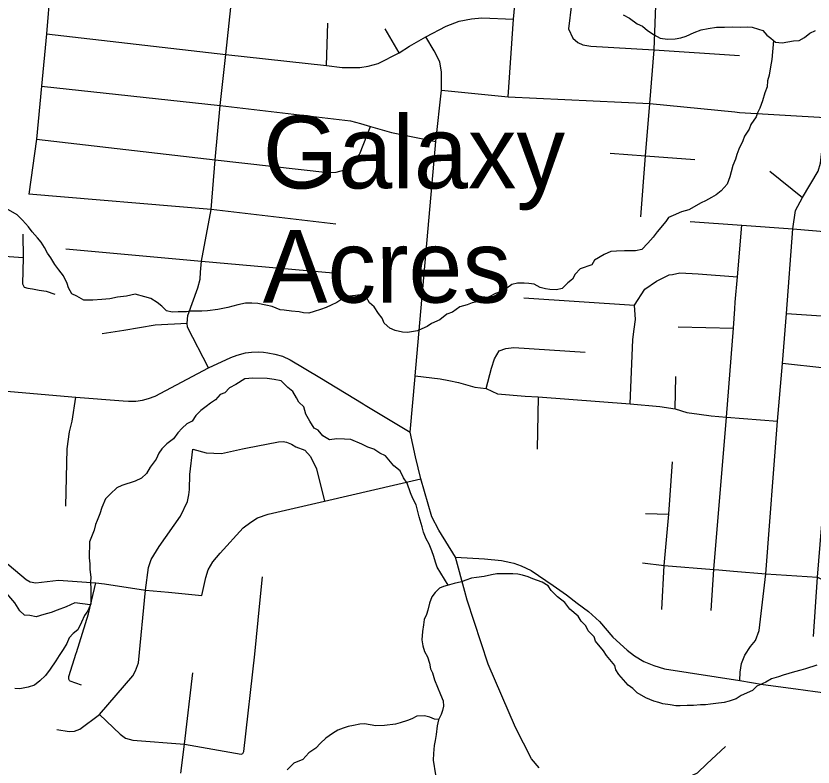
# Model space of a CAD drawing. Extents: x 0 to 69.5, y -4.5 to 22.
# Drawn here: x 4.554 to 5.421, y 16.285 to 17.102 of the extents above; entities that cross this region are included whole.
import ezdxf

# ---------------------------------------------------------------- set-up
doc = ezdxf.new("R2010")
doc.units = 0
for name, color, linetype in [('GM_X_County_Road', 7, 'Continuous'), ('GM_X_Minor_River', 7, 'Continuous'), ('GM_X_Township_Subdivision', 7, 'Continuous'), ('GM_X_Unincorporated_Text', 7, 'Continuous')]:
    doc.layers.add(name, color=color, linetype=linetype)

msp = doc.modelspace()

# ---------------------------------------------------------------- linework, layer by layer
at = {"layer": 'GM_X_County_Road'}
for points in [[(4.98809, 16.70952), (4.98815, 16.71012), (5.01058, 16.96502), (5.01675, 17.02076), (5.08927, 17.01363), (5.09515, 17.09796), (5.11236, 17.27796)], [(5.08927, 17.01363), (5.24337, 17.00629), (5.33573, 16.9972)], [(5.33573, 16.9972), (5.34088, 16.9967), (5.4342, 16.99118), (5.44574, 16.99168), (5.45778, 16.99319), (5.47383, 16.99921), (5.48558, 17.00366)], [(4.5229, 16.69542), (4.6194, 16.68687), (4.67069, 16.68292), (4.67645, 16.68276), (4.68435, 16.68276), (4.69158, 16.68358), (4.69815, 16.68539), (4.70555, 16.68819), (4.76358, 16.71876), (4.78792, 16.7301), (4.79466, 16.73257), (4.8037, 16.73504), (4.81044, 16.73586), (4.81734, 16.73636), (4.82327, 16.73603), (4.8282, 16.73521), (4.83576, 16.73389), (4.84414, 16.73142), (4.8522, 16.72748), (4.88475, 16.70857), (4.93159, 16.6799)], [(4.98273, 16.64889), (4.98809, 16.70952)], [(4.93159, 16.6799), (4.93391, 16.67848), (4.98273, 16.64889)], [(5.03222, 16.51309), (5.01381, 16.5422), (5.00625, 16.55682), (4.99457, 16.59809), (4.98866, 16.62209), (4.98273, 16.64889)], [(5.04216, 16.47567), (5.03222, 16.51309)], [(5.03222, 16.51309), (5.06379, 16.51128), (5.08203, 16.50931), (5.09237, 16.50719)], [(5.09237, 16.50719), (5.09568, 16.50652), (5.10341, 16.50372), (5.11443, 16.49863), (5.13842, 16.48218), (5.15273, 16.47216), (5.16457, 16.46311), (5.17673, 16.45407), (5.18882, 16.4429), (5.2032, 16.42612), (5.21866, 16.41182), (5.22671, 16.40574), (5.2369, 16.39949), (5.24792, 16.39505), (5.25926, 16.3916), (5.3413, 16.37894), (5.36662, 16.37466), (5.40213, 16.36974), (5.42309, 16.36686), (5.44274, 16.36431), (5.44492, 16.36412)], [(5.12307, 16.28389), (5.11471, 16.29382), (5.09721, 16.32776), (5.06762, 16.39671), (5.04464, 16.46635), (5.04216, 16.47567)]]:
    msp.add_lwpolyline(points, dxfattribs=at)
at = {"layer": 'GM_X_Minor_River'}
for points in [[(5.21444, 17.10287), (5.22119, 17.09925), (5.22976, 17.09292), (5.2354, 17.09048), (5.24097, 17.08575), (5.24807, 17.08098), (5.25482, 17.07737), (5.26278, 17.07639), (5.27115, 17.07654), (5.27727, 17.07789), (5.28302, 17.07963), (5.29149, 17.08359), (5.29917, 17.08642), (5.30683, 17.08811), (5.31599, 17.08937), (5.32474, 17.08951), (5.33387, 17.08964), (5.34223, 17.08941), (5.34946, 17.08959), (5.35478, 17.08944), (5.36157, 17.08734), (5.36646, 17.08569), (5.37051, 17.08062), (5.37499, 17.07745), (5.3802, 17.07312), (5.3874, 17.07254), (5.39963, 17.07448), (5.40573, 17.07507), (5.41152, 17.07834), (5.41734, 17.08275), (5.42351, 17.08562)], [(5.37806, 17.0749), (5.37626, 17.05419), (5.37452, 17.04624), (5.37313, 17.03714), (5.37145, 17.03109), (5.37089, 17.02463), (5.36843, 17.01785), (5.36591, 17.00916), (5.36303, 17.00124), (5.36062, 16.99636), (5.35898, 16.99184), (5.35343, 16.98361), (5.35138, 16.97834), (5.34624, 16.97087), (5.34458, 16.96596), (5.34015, 16.95656), (5.33809, 16.95091), (5.33644, 16.94601), (5.33358, 16.93885), (5.33187, 16.93204), (5.33059, 16.92675), (5.32771, 16.91883), (5.32105, 16.9114), (5.3156, 16.90698), (5.31058, 16.90407), (5.30402, 16.90045), (5.29939, 16.89829), (5.28588, 16.89067), (5.27784, 16.88861), (5.26898, 16.88467), (5.2636, 16.88254), (5.26082, 16.87804), (5.25139, 16.86688), (5.24704, 16.86091), (5.24117, 16.8546), (5.23489, 16.84754), (5.22801, 16.84621), (5.21584, 16.84617), (5.20708, 16.84565), (5.20099, 16.84544), (5.19367, 16.84221), (5.18324, 16.83603), (5.18043, 16.83078), (5.16777, 16.82656), (5.16229, 16.82062), (5.15948, 16.81537), (5.15443, 16.81132), (5.14817, 16.80502), (5.14205, 16.80367), (5.13484, 16.80425), (5.12991, 16.80477), (5.12425, 16.80645), (5.11751, 16.81006), (5.11182, 16.8106), (5.10689, 16.81112), (5.09966, 16.81094), (5.09353, 16.80959), (5.08384, 16.80262), (5.07578, 16.7998), (5.06883, 16.79619), (5.06269, 16.79407), (5.05576, 16.79084), (5.0504, 16.78947), (5.04463, 16.78734), (5.03697, 16.78527), (5.02883, 16.77941), (5.02269, 16.77729), (5.01491, 16.77103), (5.00606, 16.76709), (5.0014, 16.7638), (4.99563, 16.76129), (4.99063, 16.75915), (4.97993, 16.75716), (4.97462, 16.75769), (4.96668, 16.75943), (4.96066, 16.76188), (4.95472, 16.76738), (4.95221, 16.77278), (4.94854, 16.77784), (4.9438, 16.7852), (4.9386, 16.78954), (4.93533, 16.79534), (4.92856, 16.79819), (4.92322, 16.79758), (4.91674, 16.797), (4.90944, 16.79416), (4.90324, 16.79014), (4.89707, 16.78689), (4.8913, 16.78438), (4.88516, 16.78227), (4.87826, 16.78018), (4.8725, 16.77843), (4.8668, 16.77859), (4.86228, 16.77986), (4.85392, 16.78048), (4.84596, 16.78146), (4.84142, 16.78197), (4.83277, 16.78563), (4.82596, 16.78697), (4.81726, 16.78873), (4.81081, 16.7893)], [(4.81081, 16.7893), (4.80358, 16.78912), (4.79555, 16.78744), (4.78445, 16.7847), (4.77374, 16.78233), (4.76228, 16.78075), (4.75619, 16.78054), (4.75163, 16.78066), (4.74402, 16.7805), (4.73944, 16.77986), (4.73069, 16.77973), (4.72384, 16.77954), (4.71779, 16.78085), (4.71261, 16.78594), (4.70777, 16.78988), (4.70066, 16.79427), (4.69424, 16.79597), (4.68368, 16.79894), (4.67449, 16.79691), (4.66457, 16.79566), (4.65616, 16.79399), (4.64739, 16.79309), (4.63787, 16.7926), (4.63292, 16.79236), (4.62798, 16.79249), (4.62049, 16.79689), (4.61485, 16.79933), (4.61123, 16.80591), (4.60984, 16.81052), (4.60588, 16.81901), (4.60074, 16.82562), (4.59633, 16.83146), (4.59196, 16.83844), (4.58829, 16.84349), (4.58504, 16.84967), (4.58139, 16.85548), (4.57772, 16.86016), (4.57181, 16.8668), (4.56778, 16.87224), (4.56113, 16.87966), (4.55558, 16.88515), (4.5436, 16.89234)], [(5.0243, 16.48247), (5.01218, 16.50226), (5.01042, 16.50764), (5.00869, 16.51378), (5.0062, 16.51995), (5.00335, 16.52726), (5.00009, 16.53306), (4.99723, 16.54), (4.99588, 16.54613), (4.99274, 16.55688), (4.9893, 16.56992), (4.98568, 16.57688), (4.98319, 16.58304), (4.97967, 16.59342), (4.97564, 16.59924), (4.97205, 16.60696), (4.96497, 16.61249), (4.95613, 16.62302), (4.94975, 16.62624), (4.94341, 16.63061), (4.93662, 16.6327), (4.93024, 16.63593), (4.91821, 16.64083), (4.91138, 16.6414), (4.90302, 16.64164), (4.89501, 16.64072), (4.8879, 16.6451), (4.88274, 16.65096), (4.87824, 16.65337), (4.87387, 16.66073), (4.86952, 16.66846), (4.86708, 16.67653), (4.86189, 16.68162), (4.85935, 16.68626), (4.85536, 16.69323), (4.84977, 16.69758), (4.84236, 16.70464), (4.8348, 16.70637), (4.82722, 16.70734), (4.81164, 16.70778), (4.80287, 16.70688), (4.7932, 16.70068), (4.78625, 16.69706), (4.78117, 16.69187), (4.77617, 16.68973), (4.77107, 16.68416), (4.76565, 16.6805), (4.76098, 16.67682), (4.75516, 16.67242), (4.7497, 16.66724), (4.74572, 16.66087), (4.73994, 16.65799), (4.73486, 16.65318), (4.73017, 16.64836), (4.72542, 16.64164), (4.71805, 16.63613), (4.71258, 16.63095), (4.70941, 16.62609), (4.70657, 16.6197), (4.70025, 16.61073), (4.69626, 16.60399), (4.69079, 16.59881), (4.68386, 16.59558), (4.66929, 16.59104), (4.6639, 16.58852), (4.65687, 16.58186), (4.65139, 16.5763), (4.64734, 16.5669), (4.64525, 16.5601), (4.64239, 16.55294), (4.64075, 16.54842), (4.63906, 16.54237), (4.63621, 16.53522), (4.63415, 16.52956), (4.63369, 16.51244), (4.63464, 16.50556), (4.63448, 16.49947), (4.63539, 16.49107), (4.63525, 16.48574), (4.63542, 16.47812), (4.63563, 16.47164), (4.63537, 16.46213), (4.63212, 16.4546), (4.62856, 16.44937), (4.62532, 16.44223), (4.62129, 16.43396), (4.61624, 16.42991), (4.61192, 16.42508), (4.60948, 16.41906), (4.6055, 16.41269), (4.60114, 16.40596), (4.59756, 16.40035), (4.59122, 16.39101), (4.5861, 16.38429), (4.58023, 16.37837), (4.57441, 16.37396), (4.5675, 16.37148), (4.55833, 16.36984), (4.55301, 16.36999)], [(4.63495, 16.46116), (4.61829, 16.46337), (4.60866, 16.45907), (4.59906, 16.45552), (4.59252, 16.45266), (4.58448, 16.4506), (4.57604, 16.44817), (4.56923, 16.4495), (4.56354, 16.45004), (4.55835, 16.45476), (4.55288, 16.46329), (4.54624, 16.47109), (4.5422, 16.47615), (4.53667, 16.48278), (4.53263, 16.48784), (4.52933, 16.49251), (4.52263, 16.49802), (4.50969, 16.50217)], [(5.18454, 16.42168), (5.18277, 16.4263), (5.17648, 16.43295), (5.17397, 16.43835), (5.16878, 16.44344), (5.16551, 16.44887), (5.15658, 16.45635), (5.15108, 16.46374), (5.14288, 16.46968), (5.13622, 16.47672), (5.13294, 16.48176), (5.1262, 16.48576), (5.11603, 16.48947), (5.11114, 16.49151), (5.10511, 16.49358), (5.09981, 16.49449), (5.09451, 16.49502), (5.08728, 16.49484), (5.08234, 16.49498), (5.07701, 16.49474), (5.07128, 16.49376), (5.06324, 16.49208), (5.05484, 16.49079), (5.0495, 16.49018), (5.04336, 16.48807), (5.03875, 16.48629), (5.03071, 16.48423), (5.02572, 16.48284), (5.01921, 16.48112), (5.0146, 16.47935), (5.00991, 16.47453), (5.00635, 16.46968), (5.00389, 16.46289), (5.00216, 16.45532), (5.00051, 16.4508), (4.99808, 16.44515), (4.99717, 16.43947), (4.99621, 16.43226), (4.99558, 16.42314), (4.99655, 16.41664), (4.99828, 16.4105), (5.00155, 16.40469), (5.00402, 16.39777), (5.00499, 16.39165), (5.00715, 16.38702), (5.00924, 16.37973), (5.01564, 16.36355), (5.01888, 16.35661), (5.0191, 16.35089), (5.01784, 16.34636), (5.01657, 16.34182), (5.01376, 16.33619), (5.01205, 16.32938), (5.01105, 16.32027), (5.0101, 16.31344), (5.00881, 16.30815), (5.0082, 16.29941), (5.008, 16.29218), (5.01023, 16.27612)], [(5.42494, 16.39556), (5.41267, 16.39172), (5.40767, 16.38995), (5.40078, 16.38824), (5.38852, 16.38477), (5.38353, 16.38301), (5.37585, 16.38056), (5.36967, 16.37692), (5.35967, 16.37263), (5.35497, 16.36781), (5.34266, 16.36244), (5.33723, 16.35878), (5.32956, 16.35633), (5.3242, 16.35496), (5.31504, 16.35369), (5.30932, 16.35309), (5.30398, 16.35248), (5.29865, 16.35224), (5.29103, 16.35169), (5.28418, 16.3515), (5.27657, 16.35133), (5.27163, 16.35147), (5.26557, 16.3524), (5.25761, 16.35338), (5.25309, 16.35503), (5.2478, 16.35632), (5.23915, 16.35999), (5.2298, 16.36558), (5.22498, 16.37029), (5.21975, 16.37386), (5.20981, 16.38556), (5.20652, 16.3906), (5.2055, 16.3952), (5.19629, 16.40612), (5.19301, 16.41116), (5.18454, 16.42168)], [(5.01396, 16.33659), (5.00921, 16.3367), (5.00433, 16.33912), (4.99828, 16.34043), (4.9899, 16.3399), (4.9845, 16.337), (4.97989, 16.33523), (4.97183, 16.33279), (4.96685, 16.3314), (4.95502, 16.32983), (4.94551, 16.32971), (4.93945, 16.33064), (4.93301, 16.33159), (4.92806, 16.33134), (4.92118, 16.33001), (4.91544, 16.32865), (4.91007, 16.32689), (4.90431, 16.32477), (4.8985, 16.32112), (4.89114, 16.316), (4.88529, 16.31083), (4.8802, 16.30526), (4.87246, 16.30014), (4.86618, 16.29308), (4.85617, 16.28879), (4.84914, 16.28175)]]:
    msp.add_lwpolyline(points, dxfattribs=at)
at = {"layer": 'GM_X_Township_Subdivision'}
for points in [[(5.2336, 16.88318), (5.23886, 16.94949), (5.24337, 17.00629), (5.24801, 17.06473), (5.24996, 17.11306), (5.25136, 17.12144), (5.25535, 17.13142), (5.2753, 17.16534), (5.30483, 17.21722)], [(4.59116, 17.13115), (4.58739, 17.08214), (4.58173, 17.02521), (4.57646, 16.96752), (4.5683, 16.90769)], [(5.1581, 17.11458), (5.15485, 17.0876), (5.15982, 17.07727), (5.16514, 17.0729), (5.17054, 17.07016), (5.17932, 17.06876), (5.24801, 17.06473), (5.34095, 17.05858)], [(4.76358, 16.71876), (4.74063, 16.76321), (4.74033, 16.76765), (4.74107, 16.77578), (4.75204, 16.80587), (4.75456, 16.81531), (4.75475, 16.82291), (4.75594, 16.83508), (4.76629, 16.89117), (4.77063, 16.94509), (4.77628, 17.00418), (4.7825, 17.05961), (4.78797, 17.1107)], [(4.58739, 17.08214), (4.7825, 17.05961), (4.89175, 17.04782), (4.90872, 17.04538), (4.92813, 17.04538), (4.93699, 17.04698), (4.94793, 17.0499), (4.97074, 17.06159), (4.98206, 17.06886), (4.9997, 17.07897), (5.02211, 17.09062), (5.03599, 17.09596), (5.04961, 17.09862), (5.06076, 17.0995), (5.09515, 17.09796)], [(4.89175, 17.04782), (4.89322, 17.09371)], [(4.97074, 17.06159), (4.95575, 17.0876)], [(5.01675, 17.02076), (5.01705, 17.04057), (5.01492, 17.05172), (5.00891, 17.06376), (4.9997, 17.07897)], [(4.58173, 17.02521), (4.77628, 17.00418), (4.91786, 16.98741), (4.92879, 16.98477), (4.93954, 16.98137), (4.95236, 16.9776), (4.96254, 16.97478), (5.01058, 16.96502)], [(5.3413, 16.37894), (5.34163, 16.38798), (5.34295, 16.39752), (5.34689, 16.4064), (5.35281, 16.41577), (5.35825, 16.4223), (5.36231, 16.43329), (5.36946, 16.49489), (5.38216, 16.66076), (5.38756, 16.7235), (5.39207, 16.7781), (5.39883, 16.87016), (5.40181, 16.89013), (5.4096, 16.90411), (5.42641, 16.93278), (5.42906, 16.94163), (5.43137, 16.96075), (5.4342, 16.99118)], [(4.57646, 16.96752), (4.77063, 16.94509), (4.89316, 16.93142), (4.9024, 16.9316), (4.91164, 16.93424), (4.92013, 16.94148), (4.92766, 16.95102), (4.93238, 16.9629), (4.93954, 16.98137)], [(5.20039, 16.95252), (5.23886, 16.94949), (5.29223, 16.94545)], [(5.37384, 16.93296), (5.4096, 16.90411)], [(4.90215, 16.87508), (4.76629, 16.89117), (4.5683, 16.90769)], [(5.28716, 16.87821), (5.34366, 16.87393), (5.39883, 16.87016), (5.45446, 16.86522), (5.48021, 16.86333)], [(5.33638, 16.79021), (5.33862, 16.81775), (5.34366, 16.87393)], [(4.56151, 16.86418), (4.56211, 16.83865), (4.56136, 16.81039), (4.56299, 16.80655), (4.56714, 16.80537), (4.57216, 16.80492), (4.57941, 16.8033), (4.58695, 16.80241), (4.59657, 16.79886)], [(5.39207, 16.7781), (5.43543, 16.77527), (5.44446, 16.77438), (5.44836, 16.7773), (5.45446, 16.86522)], [(4.56211, 16.83865), (4.43076, 16.84811), (4.33929, 16.85497)], [(4.60854, 16.84819), (4.75594, 16.83508), (4.89892, 16.82236)], [(5.22643, 16.76078), (5.22776, 16.77165), (5.22677, 16.78695), (5.2381, 16.8043), (5.25084, 16.81314), (5.26465, 16.81987), (5.26792, 16.82058)], [(5.26792, 16.82058), (5.27597, 16.82235), (5.29615, 16.82128), (5.33862, 16.81775)], [(5.10642, 16.79509), (5.22677, 16.78695)], [(5.31011, 16.45509), (5.31318, 16.49968), (5.32677, 16.66518), (5.33438, 16.76217), (5.3358, 16.78306), (5.33638, 16.79021)], [(4.64775, 16.75641), (4.67126, 16.75981), (4.70558, 16.76558), (4.74033, 16.76765)], [(5.22217, 16.6797), (5.22509, 16.74976), (5.22643, 16.76078)], [(5.27421, 16.76359), (5.33438, 16.76217)], [(5.06536, 16.69633), (5.07138, 16.71863), (5.07457, 16.72855), (5.07952, 16.73739), (5.08696, 16.73987), (5.09545, 16.74094), (5.17297, 16.73598)], [(5.42134, 16.42689), (5.42563, 16.49126), (5.44393, 16.71306), (5.44039, 16.7166), (5.43357, 16.71837), (5.38756, 16.7235)], [(4.98815, 16.71012), (5.01545, 16.70695), (5.02501, 16.70518), (5.03528, 16.70306), (5.05297, 16.69775), (5.06536, 16.69633), (5.07775, 16.69067), (5.10784, 16.68819), (5.122, 16.68748), (5.22217, 16.6797), (5.25438, 16.67687), (5.27102, 16.67439), (5.28376, 16.6705), (5.29721, 16.66837), (5.31031, 16.6666), (5.32677, 16.66518), (5.38216, 16.66076)], [(5.27102, 16.67439), (5.27173, 16.70941)], [(4.5229, 16.69542), (4.50929, 16.53767), (4.50998, 16.53461), (4.51401, 16.53143), (4.56536, 16.48879), (4.56947, 16.48603), (4.57589, 16.4851), (4.6004, 16.48797), (4.64111, 16.48524), (4.65046, 16.48382)], [(4.60835, 16.56863), (4.60991, 16.63088), (4.61227, 16.64944), (4.61522, 16.66076), (4.6194, 16.68687)], [(5.122, 16.68748), (5.121, 16.63034)], [(4.80397, 16.63155), (4.83966, 16.63847), (4.84482, 16.63861), (4.8482, 16.63799), (4.85359, 16.63598), (4.85861, 16.6331), (4.86839, 16.62936), (4.87435, 16.62248), (4.88092, 16.60903), (4.88965, 16.57381)], [(4.74206, 16.58094), (4.74301, 16.58654), (4.74312, 16.60292), (4.74641, 16.63049)], [(4.74641, 16.63049), (4.76099, 16.62639), (4.77763, 16.62577), (4.80061, 16.6309), (4.80397, 16.63155)], [(5.25664, 16.45604), (5.25889, 16.5039), (5.26412, 16.55983), (5.26827, 16.6168)], [(4.75626, 16.47134), (4.76044, 16.49078), (4.76331, 16.49906), (4.76809, 16.50806), (4.77629, 16.51735), (4.80134, 16.54476), (4.80945, 16.55112), (4.81674, 16.55595), (4.82845, 16.55985), (4.88965, 16.57381), (4.99457, 16.59809)], [(4.59855, 16.32553), (4.6119, 16.32328), (4.61765, 16.32389), (4.62349, 16.3259), (4.64496, 16.34196), (4.68111, 16.38411), (4.68428, 16.38935), (4.68754, 16.39801), (4.69503, 16.47705), (4.69815, 16.50173), (4.70102, 16.51056), (4.70985, 16.52473), (4.73306, 16.55759), (4.74084, 16.57369), (4.74206, 16.58094)], [(5.23883, 16.5606), (5.26412, 16.55983)], [(5.23533, 16.50672), (5.25889, 16.5039), (5.31318, 16.49968), (5.31861, 16.4992)], [(5.31861, 16.4992), (5.33429, 16.49781), (5.36946, 16.49489), (5.42563, 16.49126), (5.45133, 16.47875)], [(4.64496, 16.34196), (4.66734, 16.3206), (4.67309, 16.31609), (4.6811, 16.31382), (4.73723, 16.30953), (4.79888, 16.29876), (4.80079, 16.29946), (4.80199, 16.30172), (4.81375, 16.4074), (4.81941, 16.46305), (4.82231, 16.49152)], [(4.61966, 16.40867), (4.61982, 16.40917), (4.6331, 16.4514), (4.64111, 16.48524)], [(4.65046, 16.48382), (4.69503, 16.47705), (4.72012, 16.47483), (4.75626, 16.47134)], [(4.62546, 16.37372), (4.61325, 16.37801), (4.61219, 16.37884), (4.61163, 16.38014), (4.61151, 16.38177), (4.61166, 16.38318), (4.61966, 16.40867)], [(4.73347, 16.27797), (4.73723, 16.30953), (4.74646, 16.38705)], [(5.29556, 16.057), (5.30138, 16.12428), (5.2767, 16.21349), (5.26067, 16.26464), (5.26206, 16.26842), (5.26583, 16.27001), (5.28507, 16.27377), (5.29544, 16.27845), (5.30554, 16.28807), (5.32575, 16.30695)]]:
    msp.add_lwpolyline(points, dxfattribs=at)

# ---------------------------------------------------------------- texts
at = {"layer": 'GM_X_Unincorporated_Text'}
for s, p in [('Galaxy', (4.82253, 16.91402)), ('Acres', (4.82253, 16.78985))]:
    msp.add_text(s, height=0.078977, rotation=0.00001, dxfattribs=at).set_placement(p)

doc.saveas('drawing.dxf')
